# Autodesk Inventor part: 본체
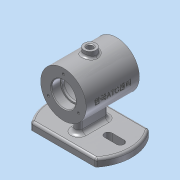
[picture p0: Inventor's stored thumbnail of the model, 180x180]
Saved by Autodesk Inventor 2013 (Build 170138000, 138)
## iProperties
Created: 2017-12
Part Number: 본체
Material: 알루미늄 6061
Document SubType Name: Modeling
Designer: dgall
Mass: 461.243 g
Surface Area: 484.663 cm^2
Volume: 170.201 cm^3
Density: 2.71 g/cm^3
Author: dgall
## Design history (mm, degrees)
sketch "스케치1"
  geometry: L1 (0, 0)-(70, 0); L2 (0, 0)-(0, 30); L3 (0, 30)-(70, 30); L4 (70, 30)-(70, 0); L5 (0, 16)-(11.7, 16); L6 (12, 15.7)-(12, 14); L7 (12, 14)-(15, 14); L8 (15, 14)-(15, 22); L9 (18, 25)-(52, 25); L10 (55, 22)-(55, 14); L11 (55, 14)-(58, 14); L12 (58, 14)-(58, 15.7); L13 (58.3, 16)-(70, 16); A1 r 3 centre (18, 22) between (18, 25) and (15, 22); A2 r 3 centre (52, 22) between (55, 22) and (52, 25); A3 r 0.3 centre (11.7, 15.7) between (12, 15.7) and (11.7, 16); A4 r 0.3 centre (58.3, 15.7) between (58.3, 16) and (58, 15.7); 5 further points
  constraints: 27 end point, 10 point on line, 8 point on circle, 8 tangent, 6 parallel, 5 perpendicular, 4 centre point, 2 collinear, 1 coincident, 1 equal radius, 1 horizontal
  dimensions: "d0" = 70 distance of L1.start L1.end; "d2" = 50 diameter of L9 L1; "d3" = 12 distance of L5.start point (12, 16); "d4" = 40 distance of point (15, 25) point (55, 25); "d5" = 12 distance of point (58, 16) L13.end; "d6" = 32 diameter of L5 L1; "d7" = 32 diameter of L13 L1; "d8" = 28 diameter of L11 L1; "d9" = 28 diameter of L7 L1; "d10" = 60 diameter of L3 L1; "d11" = 3 radius of A1; "d12" = 0.3 radius of A3; "d13" = 0.3 radius of A4
revolve "회전1" sketch "스케치1" stored, may be unused: angle "d14" = 90 deg
chamfer "모따기1" distance "d15" = 1; stored, may be unused: second distance "d16" = 2, angle "d17" = 45 deg
node "작업 평면1"
sketch "스케치2"
  geometry: L1 (0, -30)-(0, 30) reference; L2 (0, 42.426)-(0, -42.426); L3 (70, 42.426)-(70, -42.426); L4 (0, 30)-(70, 30) reference; A1 r 55 centre (35, 0) between (0, 42.426) and (0, -42.426); 3 further points
  constraints: 4 end point, 4 point on circle, 2 midpoint, 2 parallel, 1 centre point, 1 collinear, 1 horizontal alignment, 1 vertical alignment
  dimensions: "d19" = 110 diameter of A1; "d20" = 70 distance between parallel lines of L3 L2
extrude "돌출1" join sketch "스케치2" distance "d21" = 10; taper "d22" = 0 deg
sketch "스케치3"
  geometry: L1 (0, 17)-(-1, 16) reference; L2 (-1, 16)-(-11.7, 16) reference; L3 (-12, 15.7)-(-12, 14) reference; L4 (-12, 14)-(-15, 14) reference; L5 (-15, 14)-(-15, 22) reference; L6 (-18, 25)-(-52, 25) reference; L7 (-55, 22)-(-55, 14) reference; L8 (-55, 14)-(-58, 14) reference; L9 (-58, 14)-(-58, 15.7) reference; L10 (-58.3, 16)-(-69, 16) reference; L11 (-69, 16)-(-70, 17) reference; L12 (-70, 17)-(-70, 30) reference; L13 (-70, 30)-(0, 30) reference; L14 (0, 30)-(0, 17) reference; L15 (-1, -16)-(0, -17) reference; L16 (0, -17)-(0, -30) reference; L17 (0, -30)-(-70, -30) reference; L18 (-70, -30)-(-70, -17) reference; L19 (-70, -17)-(-69, -16) reference; L20 (-69, -16)-(-58.3, -16) reference; L21 (-58, -15.7)-(-58, -14) reference; L22 (-58, -14)-(-55, -14) reference; L23 (-55, -14)-(-55, -22) reference; L24 (-52, -25)-(-18, -25) reference; L25 (-15, -22)-(-15, -14) reference; L26 (-15, -14)-(-12, -14) reference; L27 (-12, -14)-(-12, -15.7) reference; L28 (-11.7, -16)-(-1, -16) reference; L29 (0, -52)-(0, -62) reference; L30 (0, -62)-(-70, -62) reference; L31 (-70, -62)-(-70, -52) reference; L32 (-70, -52)-(0, -52) reference; L33 (-55, -27)-(-55, -52); L34 (0, -52)-(-70, -52) reference; L35 (-55, -27)-(-15, -27); L36 (-15, -27)-(-15, -52); L37 (-15, -52)-(-55, -52); A1 r 0.3 centre (-11.7, 15.7) between (-11.7, 16) and (-12, 15.7) reference; A2 r 3 centre (-18, 22) between (-15, 22) and (-18, 25) reference; A3 r 3 centre (-52, 22) between (-52, 25) and (-55, 22) reference; A4 r 0.3 centre (-58.3, 15.7) between (-58, 15.7) and (-58.3, 16) reference; A5 r 0.3 centre (-58.3, -15.7) between (-58.3, -16) and (-58, -15.7) reference; A6 r 3 centre (-52, -22) between (-55, -22) and (-52, -25) reference; A7 r 3 centre (-18, -22) between (-18, -25) and (-15, -22) reference; A8 r 0.3 centre (-11.7, -15.7) between (-12, -15.7) and (-11.7, -16) reference; 3 further points
  constraints: 8 end point, 3 perpendicular, 2 midpoint, 2 point on line, 1 collinear, 1 vertical alignment
  dimensions: "d23" = 40 distance of L33.start L35.end; "d25" = 25 distance of L35.end L36.end
extrude "돌출2" join sketch "스케치3" stored distance "d26" = 10; taper "d27" = 0 deg
sketch "스케치4"
  geometry: C1 r 30 at (0, 0) reference; 1 further point
  constraints: 1 horizontal alignment
  dimensions: "d28" = 23 distance of point (-23, 0) C1.centre
hole "구멍1" sketch "스케치4" at (-23, 0) diameter "d29" = 3.242; stored, may be unused: countersink angle "d33" = 90 deg, drill point angle "d35" = 118 deg; dims "d30" = 8, "d31" = 4, "d32" = 2, "d34" = 10
node "작업 평면2"
node "작업 평면3"
sketch "스케치5"
  geometry: L1 (0, -30)-(0, 30) reference; C1 r 8 at (35, 0); 1 further point
  constraints: 1 centre point, 1 horizontal alignment
  dimensions: "d40" = 16 diameter of C1; "d41" = 35 distance from line of C1.centre L1
extrude "돌출3" join sketch "스케치5" stored distance "d42" = 10; taper "d43" = 0 deg
hole "구멍2" diameter "d46" = 8; stored, may be unused: countersink angle "d50" = 90 deg, drill point angle "d52" = 0 deg; dims "d44" = 10, "d45" = 10, "d47" = 8, "d48" = 4, "d49" = 2, "d51" = 10
chamfer "모따기2" distance "d53" = 1; stored, may be unused: second distance "d54" = 2, angle "d55" = 45 deg
fillet "모깎기1" dims "d56" = 5
fillet "모깎기2" dims "d57" = 5
fillet "모깎기3" dims "d58" = 3
fillet "모깎기4" dims "d59" = 3
sketch "스케치6"
  geometry: L1 (67, 40.988)-(67, -40.988) reference; L2 (30, 40)-(30, 24); L3 (40, 24)-(40, 40); A1 r 10 centre (50, 0) between (50, -10) and (50, 10) reference; A2 r 52 centre (35, 0) between (3, -40.988) and (67, -40.988) reference; A3 r 5 centre (35, 24) between (30, 24) and (40, 24); A4 r 5 centre (35, 40) between (40, 40) and (30, 40); 1 further point
  constraints: 4 end point, 4 point on circle, 4 tangent, 2 centre point, 2 parallel, 2 vertical alignment
  dimensions: "d60" = 5 radius of A4; "d62" = 16 distance of A3.centre A4.centre; "d63" = 24 vertical distance of A1.centre A3.centre
extrude "돌출4" cut sketch "스케치6" stored distance "d64" = 10; taper "d65" = 0 deg
node "작업 평면4"
sketch "스케치7"
  geometry: L1 (-70, 30)-(-70, -30) reference; 2 further points
  constraints: 1 other
  dimensions: "d67" = 35 distance from line of L1 point (-35, 0); "d68" = 30 vertical distance of L1.start point (-35, 0)
feature "엠보싱1" sketch "스케치7" dims "d0" = 70, "d2" = 50, "d3" = 12, "d4" = 40, "d5" = 12, "d6" = 32, "d7" = 32, "d8" = 28, "d9" = 28, "d10" = 60, "d11" = 3, "d12" = 0.3, "d13" = 0.3, "d69" = 0.5, "d70" = 0
fillet "모깎기5" dims "d71" = 3
node "솔리드1"
pattern_circular "원형 패턴1" dims angle "d37" = 360 deg
mirror "대칭1"
mirror "대칭2"
node "절단 모서리 투영1"
other parameters: "d18" = -62, "d39" = 37
